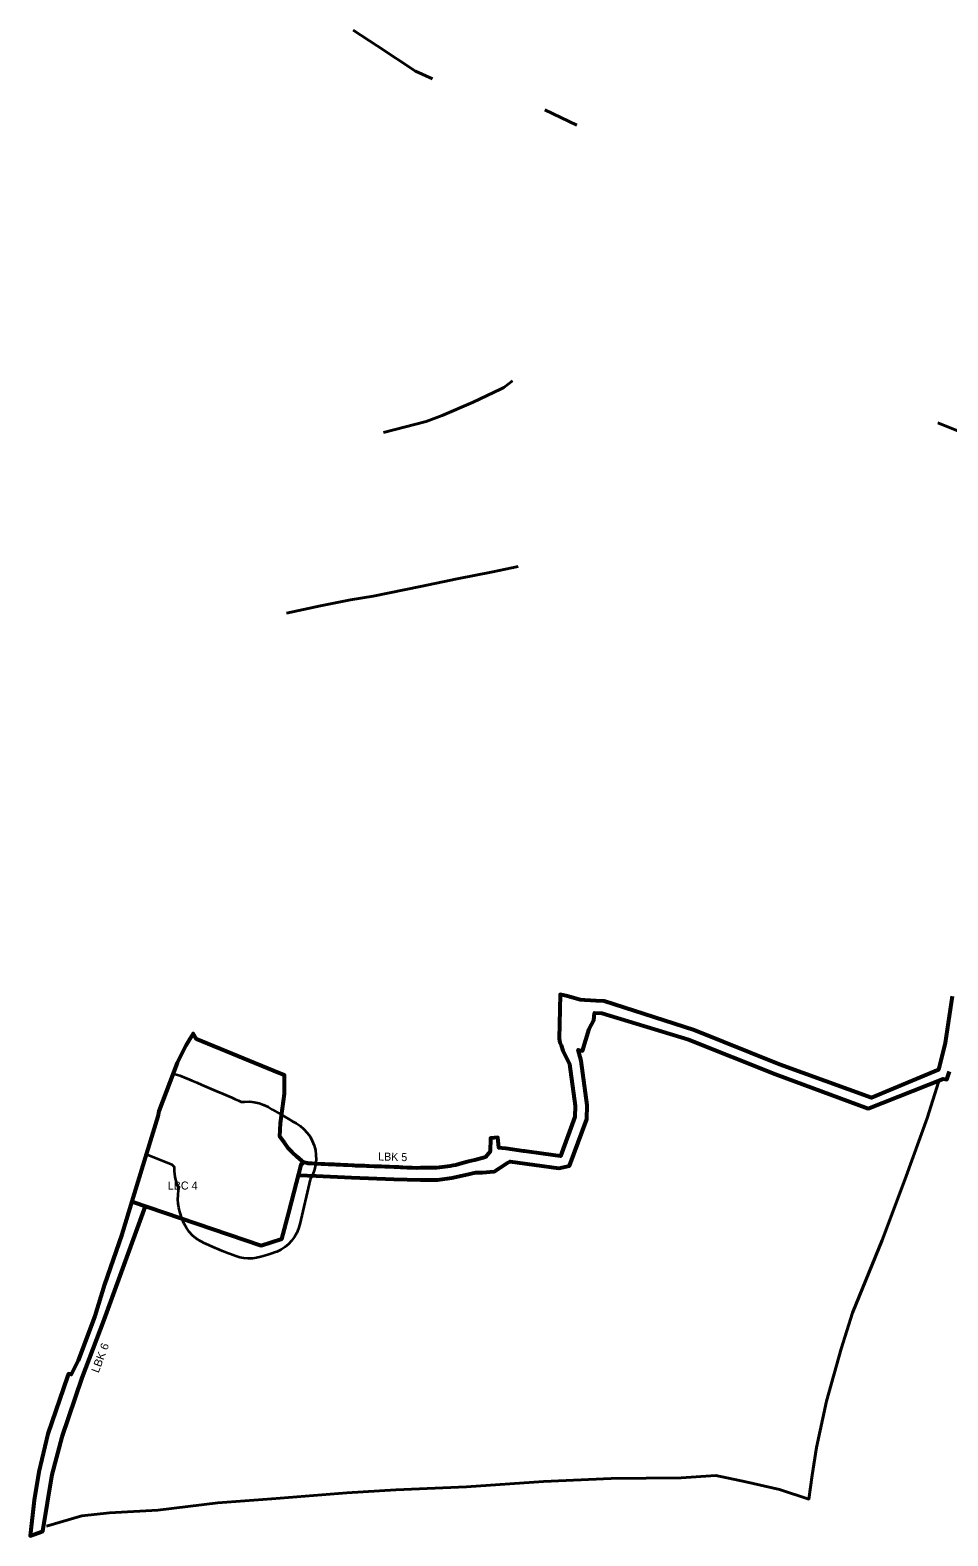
# Model space of a CAD drawing. Extents: x -555426 to -553015, y -1186745 to -1182687.
# Drawn here: x -555426 to -554278, y -1186725 to -1184843 of the extents above; entities that cross this region are included whole.
import ezdxf
from ezdxf.enums import TextEntityAlignment as Align

# ---------------------------------------------------------------- set-up
doc = ezdxf.new("R2010")
doc.units = 0
doc.header["$LTSCALE"] = 4
for name, color, linetype, lineweight in [('12', 7, 'Continuous', 53), ('14', 7, 'Continuous', 53), ('51', 7, 'Continuous', 40), ('7', 7, 'Continuous', 35)]:
    doc.layers.add(name, color=color, linetype=linetype, lineweight=lineweight)
doc.layers.add('13', color=7, linetype='Continuous')

msp = doc.modelspace()

# ---------------------------------------------------------------- linework, layer by layer
at = {"layer": '12'}
for points in [[(-554272.29, -1186050.65), (-554281.22, -1186109.23), (-554289.524, -1186142.992), (-554373.27, -1186177.71), (-554488.13, -1186136.21), (-554595.17, -1186093.44), (-554707.698, -1186057.015), (-554717.81, -1186056.56), (-554731.68, -1186055.61), (-554737.11, -1186055.23), (-554753.62, -1186050.71), (-554762.47, -1186048.86), (-554763.69, -1186104.04), (-554763.13, -1186108.53), (-554761.3, -1186111.92), (-554759.33, -1186118.73), (-554750.96, -1186135.85), (-554743.83, -1186187.67), (-554744.21, -1186201.47), (-554762.32, -1186250.8), (-554783.59, -1186247.69), (-554807.08, -1186244.72), (-554808.67, -1186244.5), (-554830.46, -1186241.38), (-554835.28, -1186240.65), (-554839.16, -1186240.36), (-554840.62, -1186227.66), (-554849.684, -1186228.237), (-554850.12, -1186244.95), (-554855.96, -1186252.02), (-554869.97, -1186255.68), (-554877.27, -1186257.56), (-554885.02, -1186259.59), (-554893.59, -1186261.84), (-554896.34, -1186262.51), (-554900.36, -1186263.12), (-554906.96, -1186263.94), (-554913.63, -1186264.75), (-554917.47, -1186265.28), (-554919.39, -1186265.33), (-554927.11, -1186265.47), (-554932.26, -1186265.55), (-554936.56, -1186265.5), (-554937.11, -1186265.47), (-554942.03, -1186265.63), (-554947.66, -1186265.42), (-554953.66, -1186265.32), (-554959.36, -1186264.92), (-554961.69, -1186264.81), (-554964.83, -1186264.67), (-554969.85, -1186264.42), (-554976.07, -1186264.1), (-554978.07, -1186264.16), (-554981.59, -1186263.95), (-554986.25, -1186263.91), (-554987.98, -1186263.78), (-554994.91, -1186263.58), (-555001.35, -1186263.21), (-555004.22, -1186263.18), (-555007.26, -1186263.05), (-555012.37, -1186262.95), (-555013.89, -1186263.01), (-555018.64, -1186262.69), (-555020.77, -1186262.57), (-555022.88, -1186262.45), (-555027.97, -1186262.21), (-555033.35, -1186261.86), (-555037.22, -1186261.67), (-555038.25, -1186261.63), (-555042.62, -1186261.45), (-555045.15, -1186261.2), (-555047.35, -1186261.3), (-555052.31, -1186261.05), (-555057.13, -1186260.95), (-555060.21, -1186260.69), (-555061.43, -1186260.68), (-555067.24, -1186260.4), (-555072.69, -1186260.16), (-555077.96, -1186259.94), (-555079.09, -1186259.62), (-555084.2, -1186258.4)], [(-555089.854, -1186274.456), (-555067.931, -1186275.384), (-555023.659, -1186277.43), (-554970.608, -1186279.401), (-554937.275, -1186280.483), (-554916.246, -1186280.253), (-554898.31, -1186277.981), (-554881.215, -1186274.099), (-554868.43, -1186271.13), (-554859.71, -1186271.15), (-554845.34, -1186269.8), (-554839.51, -1186266.06), (-554829.17, -1186259.42), (-554825.123, -1186257.297), (-554764.262, -1186265.676), (-554750.84, -1186263.055), (-554729.283, -1186204.336), (-554728.802, -1186186.849), (-554736.428, -1186131.423), (-554740.112, -1186118.075), (-554734.72, -1186119), (-554726.42, -1186091.6), (-554720.62, -1186080.75), (-554719.544, -1186071.497), (-554710.393, -1186071.909), (-554602.25, -1186105.03), (-554493.14, -1186148.4), (-554377.29, -1186191), (-554283.71, -1186153.97), (-554278.86, -1186154.79), (-554275.9, -1186144.9)], [(-555298.216, -1186307.56), (-555310.66, -1186348.84), (-555332.46, -1186411.11), (-555344.77, -1186450.74), (-555365.28, -1186506.04), (-555374.35, -1186523.58), (-555377.44, -1186522.92), (-555378.76, -1186526.22), (-555403.3, -1186597.68), (-555414.63, -1186645.4), (-555420.53, -1186680.78), (-555425.54, -1186725.43), (-555420.84, -1186723.67)], [(-555420.84, -1186723.67), (-555415.22, -1186721.67), (-555409.6, -1186719.66), (-555398.08, -1186648.64), (-555385.52, -1186601.65), (-555360.47, -1186527.99), (-555332.87, -1186455.38), (-555317.95, -1186413.97), (-555281.216, -1186313.355)]]:
    msp.add_lwpolyline(points, dxfattribs=at)
at = {"layer": '14'}
msp.add_lwpolyline([(-555298.216, -1186307.56), (-555136.764, -1186362.594), (-555110.731, -1186353.98), (-555101.91, -1186321.23), (-555086.13, -1186260.01), (-555084.7, -1186260.33), (-555084.2, -1186258.4), (-555085.48, -1186257.19), (-555091.92, -1186251.14), (-555097.77, -1186245.64), (-555102.5, -1186241.2), (-555107.16, -1186234.67), (-555111.88, -1186227.84), (-555113.1, -1186226.08), (-555112.35, -1186209.4), (-555107.58, -1186172.76), (-555107.3, -1186151.46), (-555107.27, -1186149.53), (-555108.76, -1186149.02), (-555114.26, -1186147.16), (-555217.36, -1186104.58), (-555221.63, -1186097.28), (-555227.21, -1186106.32), (-555230.94, -1186112.37), (-555241.55, -1186134.03), (-555264.37, -1186194.41), (-555265.72, -1186201.29), (-555286.2, -1186267.7)], close=True, dxfattribs=at)
at = {"layer": '51'}
for p, q in [((-554781.649, -1184943.063), (-554741.599, -1184962.151)), ((-554290.423, -1185334.268), (-554223.316, -1185361.296))]:
    msp.add_line(p, q, dxfattribs=at)
for points in [[(-554922.099, -1184904.025), (-554943.698, -1184894.67), (-554991.285, -1184862.791), (-555021.539, -1184843.229)], [(-554983.663, -1185346.397), (-554930.417, -1185332.306), (-554910.088, -1185324.914), (-554871.627, -1185308.282), (-554837.208, -1185292.112), (-554832.934, -1185290.033), (-554822.339, -1185281.792)], [(-554815.091, -1185513.522), (-554846.637, -1185520.208), (-554891.575, -1185529.042), (-554937.383, -1185538.692), (-554996.382, -1185550.653), (-555024.65, -1185555.546), (-555062.485, -1185562.884), (-555104.949, -1185571.977)], [(-555405.092, -1186713.352), (-555360.971, -1186700.416), (-555326.089, -1186696.489), (-555265.797, -1186693.255), (-555190.721, -1186684.245), (-555123.268, -1186678.932), (-555029.48, -1186671.771), (-554968.322, -1186667.728), (-554879.849, -1186663.916), (-554783.346, -1186657.45), (-554698.798, -1186653.523), (-554611.248, -1186652.83), (-554568.05, -1186650.058), (-554530.396, -1186657.912), (-554488.181, -1186667.383), (-554451.682, -1186679.395), (-554447.293, -1186649.48), (-554441.865, -1186615.06), (-554429.391, -1186556.847), (-554411.142, -1186491.704), (-554397.166, -1186446.427), (-554360.091, -1186355.642), (-554331.563, -1186280.22), (-554303.842, -1186203.179), (-554289.384, -1186158.168)]]:
    msp.add_lwpolyline(points, dxfattribs=at)
at = {"layer": '7'}
msp.add_lwpolyline([(-555246.696, -1186147.645), (-555243.956, -1186148.208), (-555238.32, -1186150.085), (-555230.18, -1186153.345), (-555229.166, -1186153.764), (-555223.104, -1186156.347), (-555217.208, -1186158.871), (-555210.794, -1186161.56), (-555193.059, -1186169.06), (-555184.162, -1186172.834), (-555175.301, -1186176.608), (-555173.89, -1186177.234), (-555169.091, -1186179.455), (-555165.046, -1186181.318), (-555161.544, -1186183.07), (-555157.286, -1186182.754), (-555151.198, -1186182.603), (-555145.137, -1186183.194), (-555139.193, -1186184.518), (-555133.453, -1186186.554), (-555128.004, -1186189.273), (-555122.755, -1186192.305), (-555112.398, -1186198.309), (-555102.508, -1186204.028), (-555096.826, -1186207.315), (-555092.828, -1186209.629), (-555087.757, -1186212.993), (-555083.132, -1186216.948), (-555079.021, -1186221.436), (-555075.487, -1186226.39), (-555072.58, -1186231.737), (-555070.344, -1186237.397), (-555068.813, -1186243.287), (-555068.008, -1186249.319), (-555067.943, -1186255.404), (-555068.617, -1186261.453), (-555070.021, -1186267.374), (-555072.134, -1186273.081), (-555075.154, -1186279.929), (-555088.153, -1186335.75), (-555089.808, -1186341.354), (-555092.106, -1186346.727), (-555095.015, -1186351.794), (-555098.496, -1186356.488), (-555102.5, -1186360.744), (-555106.974, -1186364.503), (-555111.856, -1186367.715), (-555117.078, -1186370.335), (-555118.589, -1186370.985), (-555124.289, -1186373.04), (-555128.434, -1186374.255), (-555137.094, -1186376.801), (-555142.246, -1186378.023), (-555147.499, -1186378.694), (-555152.793, -1186378.805), (-555158.069, -1186378.356), (-555163.267, -1186377.351), (-555168.331, -1186375.802), (-555175.121, -1186373.32), (-555177.353, -1186372.442), (-555184.731, -1186369.336), (-555188.648, -1186367.693), (-555196.627, -1186364.331), (-555201.085, -1186362.454), (-555205.63, -1186360.546), (-555207.098, -1186359.928), (-555212.563, -1186357.226), (-555217.659, -1186353.879), (-555222.309, -1186349.936), (-555226.445, -1186345.456), (-555230.005, -1186340.507), (-555232.937, -1186335.161), (-555235.195, -1186329.498), (-555238.245, -1186320.248), (-555239.615, -1186315.23), (-555240.456, -1186310.098), (-555240.759, -1186304.906), (-555240.521, -1186299.71), (-555239.862, -1186292.99), (-555239.73, -1186291.638), (-555242.373, -1186283.745), (-555244.2, -1186276.553), (-555244.936, -1186269.413), (-555245.089, -1186264.444), (-555247.982, -1186261.787), (-555280.217, -1186248.596), (-555280.296, -1186248.558)], dxfattribs=at)

# ---------------------------------------------------------------- texts
at = {"layer": '13'}
msp.add_text('LBK 5', height=10, rotation=358.386, dxfattribs=at).set_placement((-554972.178, -1186256.587), align=Align.CENTER)
msp.add_text('LBC 4', height=10, dxfattribs=at).set_placement((-555234.743, -1186292.493), align=Align.CENTER)
at = {"layer": '13', "width": 1.05}
msp.add_text('LBK 6', height=10, rotation=69.423, dxfattribs=at).set_placement((-555333.264, -1186504.581), align=Align.CENTER)

doc.saveas('drawing.dxf')
